// Mitsubishi GX Works2 project: Q系列PLC与BD4523通信例程   PLC: Q02/Q02H

PROGRAM MAIN
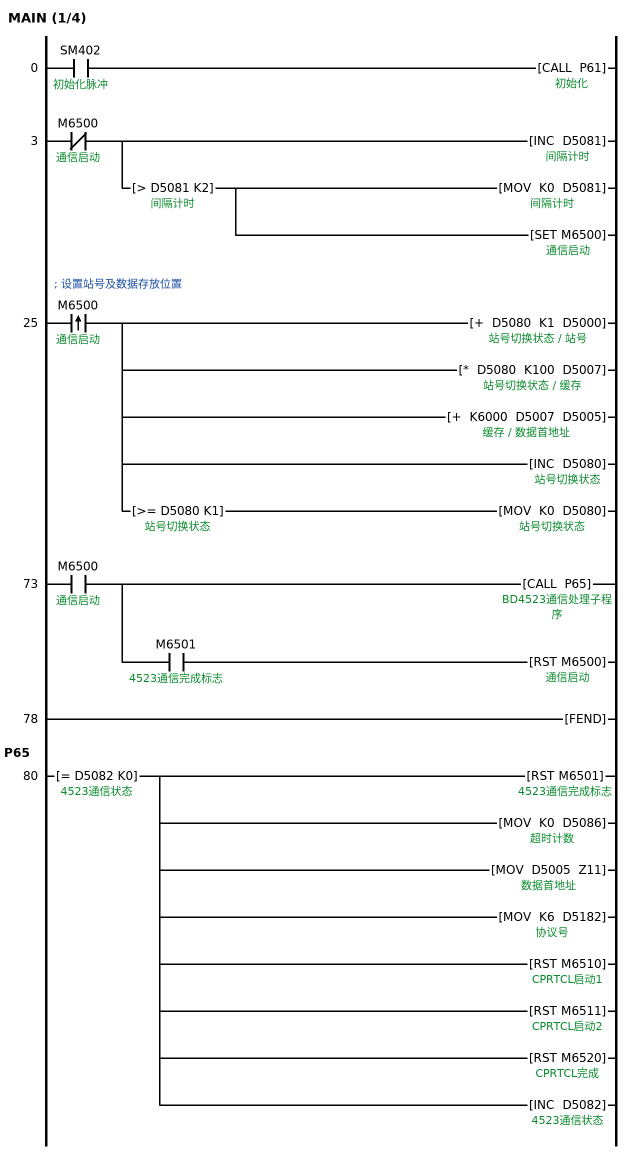
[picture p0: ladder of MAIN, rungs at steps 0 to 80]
0     LD      SM402  ; 初始化脉冲
      CALL    P61  ; 初始化
3     LDI     M6500  ; 通信启动
      INC     D5081  ; 间隔计时
      AND>    D5081 K2  ; 间隔计时
      MOV     K0 D5081
      SET     M6500  ; 通信启动
; 设置站号及数据存放位置
25    LDP     M6500  ; 通信启动
      +       D5080 K1 D5000  ; 站号切换状态 / 站号
        [note] 参与通讯站号
      *       D5080 K100 D5007  ; 缓存
      +       K6000 D5007 D5005  ; 数据首地址
        [note] 数据开始位置（D号）
      INC     D5080
      AND>=   D5080 K1  ; 站号切换状态
      MOV     K0 D5080
        [note] BD4523模块个数
73    LD      M6500  ; 通信启动
      CALL    P65  ; BD4523通信处理子程序
      AND     M6501  ; 4523通信完成标志
      RST     M6500  ; 通信启动
78    FEND
      P65
80    LD=     D5082 K0  ; 4523通信状态
      RST     M6501  ; 4523通信完成标志
      MOV     K0 D5086  ; 超时计数
      MOV     D5005 Z11
      MOV     K6 D5182  ; 协议号
      RST     M6510  ; CPRTCL启动1
      RST     M6511  ; CPRTCL启动2
      RST     M6520  ; CPRTCL完成
      INC     D5082
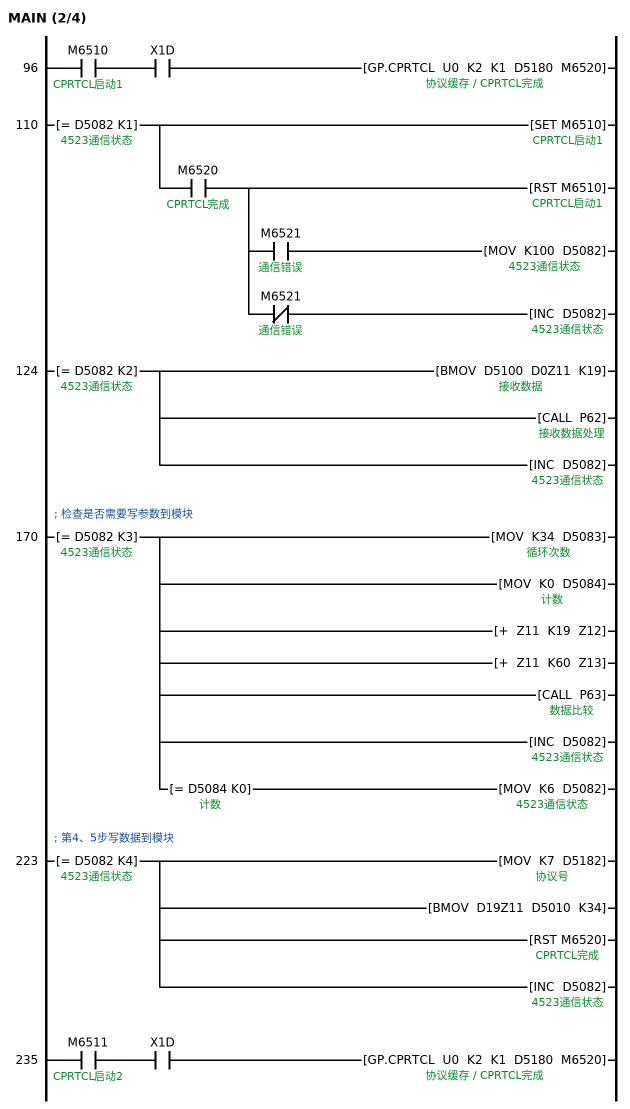
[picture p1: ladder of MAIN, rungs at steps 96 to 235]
96    LD      M6510  ; CPRTCL启动1
      AND     X1D
      GP.CPRTCL U0 K2 K1 D5180 M6520  ; 协议缓存
110   LD=     D5082 K1  ; 4523通信状态
      SET     M6510  ; CPRTCL启动1
      AND     M6520  ; CPRTCL完成
      RST     M6510  ; CPRTCL启动1
      MPS
      AND     M6521  ; 通信错误
      MOV     K100 D5082
      MPP
      ANI     M6521  ; 通信错误
      INC     D5082
124   LD=     D5082 K2  ; 4523通信状态
      BMOV    D5100 D0Z11 K19  ; 接收数据
        [note] 数据处理
      CALL    P62  ; 接收数据处理
      INC     D5082
; 检查是否需要写参数到模块
170   LD=     D5082 K3  ; 4523通信状态
      MOV     K34 D5083  ; 循环次数
      MOV     K0 D5084  ; 计数
      +       Z11 K19 Z12
      +       Z11 K60 Z13
      CALL    P63  ; 数据比较
      INC     D5082
      AND=    D5084 K0  ; 计数
      MOV     K6 D5082
; 第4、5步写数据到模块
223   LD=     D5082 K4  ; 4523通信状态
      MOV     K7 D5182
      BMOV    D19Z11 D5010 K34
      RST     M6520  ; CPRTCL完成
      INC     D5082
235   LD      M6511  ; CPRTCL启动2
      AND     X1D
      GP.CPRTCL U0 K2 K1 D5180 M6520
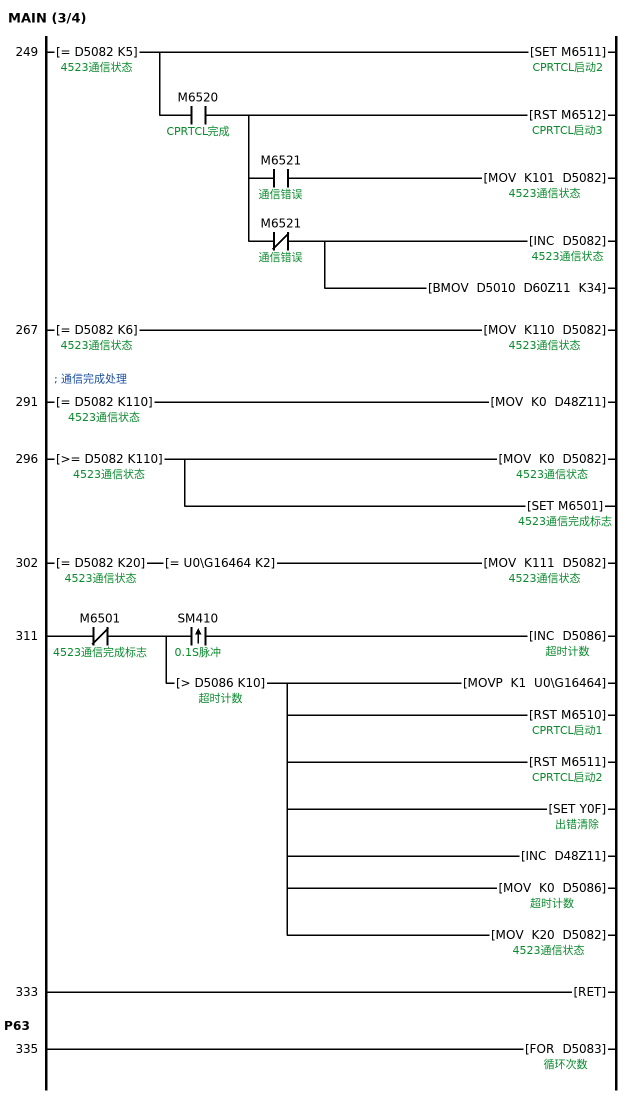
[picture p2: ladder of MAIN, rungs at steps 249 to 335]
249   LD=     D5082 K5  ; 4523通信状态
      SET     M6511  ; CPRTCL启动2
      AND     M6520  ; CPRTCL完成
      RST     M6512  ; CPRTCL启动3
      MPS
      AND     M6521  ; 通信错误
      MOV     K101 D5082
      MPP
      ANI     M6521  ; 通信错误
      INC     D5082
      BMOV    D5010 D60Z11 K34
267   LD=     D5082 K6  ; 4523通信状态
      MOV     K110 D5082
; 通信完成处理
291   LD=     D5082 K110  ; 4523通信状态
      MOV     K0 D48Z11
296   LD>=    D5082 K110  ; 4523通信状态
      MOV     K0 D5082
      SET     M6501  ; 4523通信完成标志
302   LD=     D5082 K20  ; 4523通信状态
      AND=    U0\G16464 K2
      MOV     K111 D5082
311   LDI     M6501  ; 4523通信完成标志
      MPS
      ANDP    SM410  ; 0.1S脉冲
      INC     D5086
      MPP
      AND>    D5086 K10  ; 超时计数
      MOVP    K1 U0\G16464
      RST     M6510  ; CPRTCL启动1
      RST     M6511  ; CPRTCL启动2
      SET     Y0F  ; 出错清除
      INC     D48Z11
      MOV     K0 D5086
      MOV     K20 D5082
333   RET
      P63
335   FOR     D5083
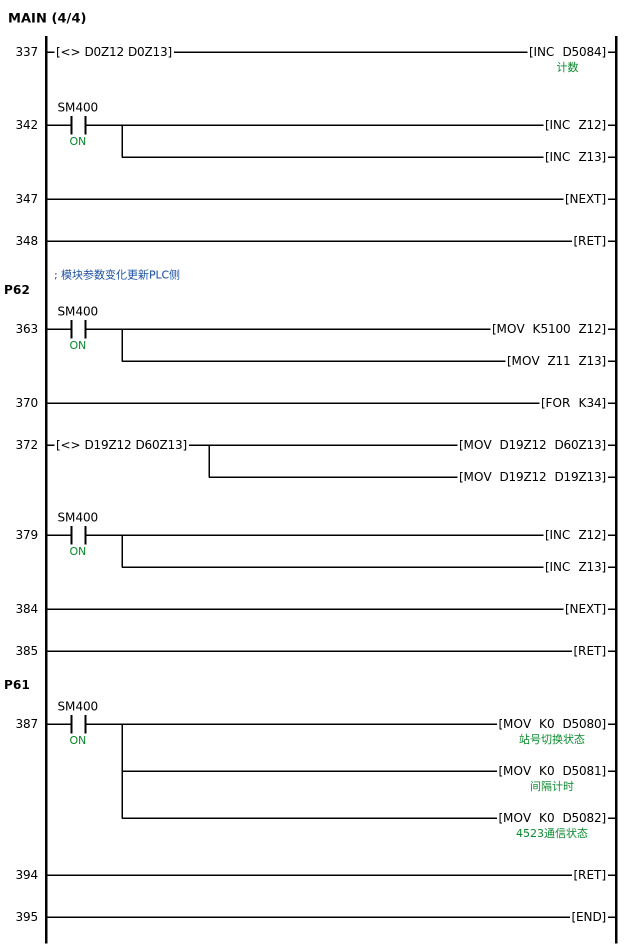
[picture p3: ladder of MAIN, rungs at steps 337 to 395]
337   LD<>    D0Z12 D0Z13
      INC     D5084
342   LD      SM400  ; ON
      INC     Z12
      INC     Z13
347   NEXT
348   RET
; 模块参数变化更新PLC侧
      P62
363   LD      SM400  ; ON
      MOV     K5100 Z12
      MOV     Z11 Z13
370   FOR     K34
372   LD<>    D19Z12 D60Z13
      MOV     D19Z12 D60Z13
      MOV     D19Z12 D19Z13
379   LD      SM400  ; ON
      INC     Z12
      INC     Z13
384   NEXT
385   RET
      P61
387   LD      SM400  ; ON
      MOV     K0 D5080
      MOV     K0 D5081
      MOV     K0 D5082
394   RET
395   END
END_PROGRAM

// device comments not shown above
X2D  ; 协议准备完成
D48  ; 通信故障计数
D5001  ; 地址
D5002  ; 数据
D5006  ; #1通道启/停M号
D5008  ; 缓存
D5085  ; 通道号
M6513  ; CPRTCL启动4
M6514  ; CPRTCL启动5
M6515  ; CPRTCL启动6
M6516  ; CPRTCL启动7
M6517  ; CPRTCL启动8
